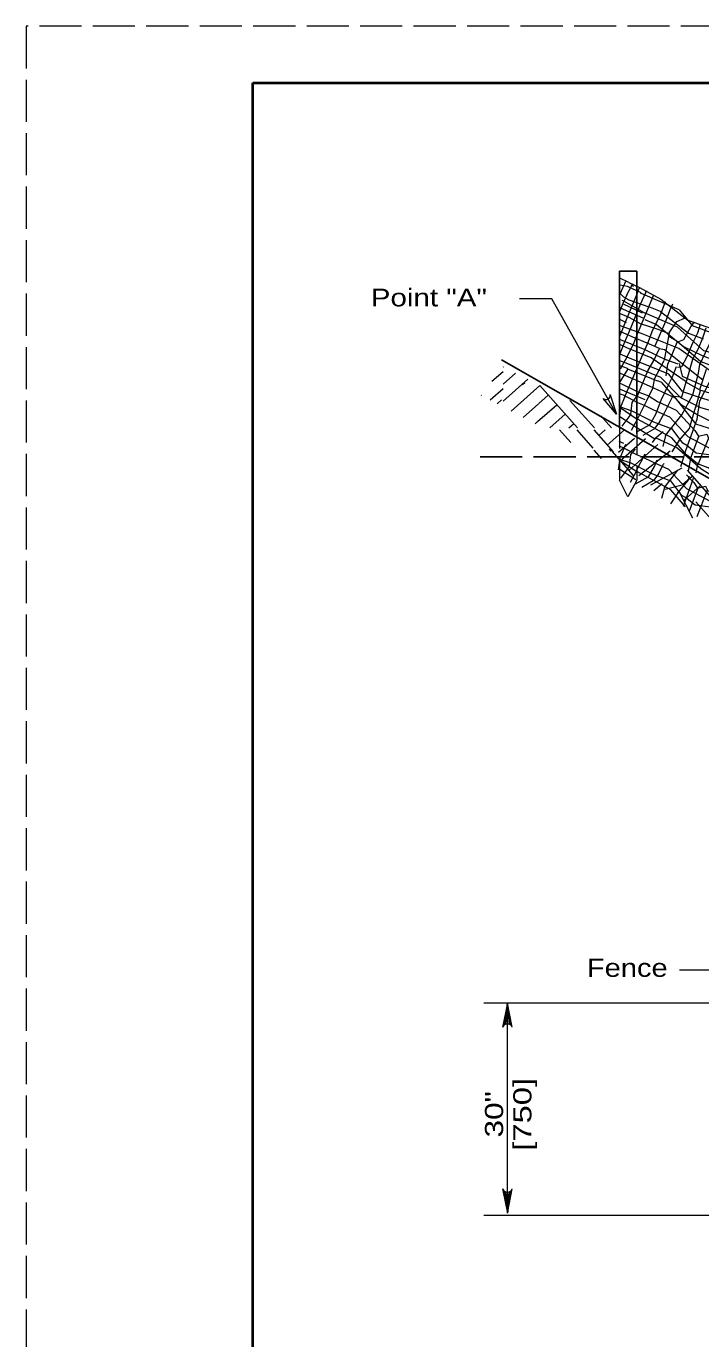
# Model space of a CAD drawing. Extents: x 1083.1 to 1117.1, y 672.5 to 716.5.
# Drawn here: x 1083.13 to 1089.08, y 704.92 to 716.51 of the extents above; entities that cross this region are included whole.
import ezdxf
from ezdxf.enums import TextEntityAlignment as Align

# ---------------------------------------------------------------- set-up
doc = ezdxf.new("R2010")
doc.units = 0
doc.header["$LTSCALE"] = 0.062
doc.linetypes.add('LONG_DASHED', pattern=[7.5, 6, -1.5])
doc.linetypes.add('MEDIUM_DASHED', pattern=[4.5, 3, -1.5])
doc.layers.add('1', color=7, linetype='Continuous', lineweight=13)

msp = doc.modelspace()

# ---------------------------------------------------------------- linework, layer by layer
at = {"layer": '1', "lineweight": 25}
for p, q in [((1085.12642, 716.00825), (1116.62642, 716.00825)), ((1088.51725, 714.345), (1088.36317, 714.345)), ((1088.36317, 714.345), (1088.36317, 712.96758)), ((1088.51725, 714.345), (1088.51725, 712.90917)), ((1091.32058, 711.27967), (1087.3225, 713.56258))]:
    msp.add_line(p, q, dxfattribs=at)
at = {"layer": '1'}
for p, q in [((1088.44675, 714.24658), (1088.36225, 714.28617)), ((1088.421, 714.25992), (1088.36758, 714.14333)), ((1088.398, 714.12), (1088.36092, 714.15842)), ((1088.43333, 714.21175), (1088.36892, 714.221)), ((1088.42842, 714.13725), (1088.4, 714.07233)), ((1088.42842, 714.13725), (1088.47292, 714.21892)), ((1088.55583, 714.15358), (1088.43333, 714.21175)), ((1088.44675, 714.24658), (1088.53967, 714.20158)), ((1088.46475, 714.22258), (1088.48883, 714.21333)), ((1088.47292, 714.21892), (1088.48192, 714.23692)), ((1088.53592, 714.19008), (1088.54733, 714.20208)), ((1088.89, 714.00417), (1088.54867, 714.15125)), ((1088.59575, 714.15667), (1088.6055, 714.17483)), ((1088.36917, 713.99683), (1088.40233, 714.07683)), ((1088.36917, 714.02367), (1088.57142, 713.93317)), ((1088.38592, 714.08875), (1088.4005, 714.08267)), ((1088.398, 714.12), (1088.44633, 714.09375)), ((1088.4005, 714.08267), (1088.58558, 713.9775)), ((1088.567, 713.97425), (1088.4005, 714.054)), ((1088.44633, 714.09375), (1088.62358, 714.0315)), ((1088.49983, 714.02608), (1088.50975, 714.02483)), ((1088.72508, 713.98917), (1088.62358, 714.0315)), ((1088.36917, 713.9715), (1088.44642, 713.93958)), ((1088.36917, 713.919), (1088.42442, 713.893)), ((1088.58742, 713.91933), (1088.69208, 713.87642)), ((1088.89, 714.00417), (1089.00758, 713.86308)), ((1088.36917, 713.86517), (1088.39417, 713.85775)), ((1088.4825, 713.76367), (1088.36917, 713.81192)), ((1088.39417, 713.85775), (1088.54575, 713.802)), ((1088.80208, 713.80267), (1088.75892, 713.56092)), ((1088.99417, 713.85517), (1089.02583, 713.898)), ((1089.19233, 713.79458), (1089.00758, 713.86308)), ((1088.36917, 713.77558), (1088.37042, 713.778)), ((1088.36917, 713.74167), (1088.58683, 713.65442)), ((1088.36917, 713.62033), (1088.41067, 713.72075)), ((1088.36917, 713.6995), (1088.459, 713.65767)), ((1088.45208, 713.57667), (1088.36917, 713.61417)), ((1088.428, 713.58592), (1088.36917, 713.47983)), ((1088.36917, 713.55383), (1088.41892, 713.537)), ((1088.64417, 713.58117), (1088.459, 713.65767)), ((1088.58683, 713.65442), (1088.77617, 713.56433)), ((1088.67025, 713.38817), (1088.75967, 713.55758)), ((1088.88167, 713.52375), (1088.77617, 713.56433)), ((1089.008, 713.5675), (1088.9525, 713.36925)), ((1087.23717, 713.37408), (1087.33567, 713.46117)), ((1087.33567, 713.49842), (1087.33883, 713.50125)), ((1087.33567, 713.34808), (1087.44725, 713.44667)), ((1088.434, 713.48558), (1088.36917, 713.50958)), ((1088.36917, 713.36858), (1088.43817, 713.4775)), ((1088.36917, 713.44517), (1088.62458, 713.3325)), ((1088.41892, 713.537), (1088.72708, 713.40967)), ((1088.43992, 713.482), (1088.434, 713.48558)), ((1088.43992, 713.482), (1088.70042, 713.37658)), ((1088.77617, 713.42058), (1088.79183, 713.52433)), ((1088.83267, 713.4145), (1088.86683, 713.50333)), ((1088.89117, 713.5305), (1088.91658, 713.41975)), ((1089.01133, 713.25308), (1089.06125, 713.445)), ((1089.08083, 713.54992), (1089.27167, 713.47908)), ((1087.33567, 713.19808), (1087.55525, 713.39217)), ((1087.40725, 713.11142), (1087.661, 713.33575)), ((1087.50883, 713.345), (1087.5285, 713.3625)), ((1087.661, 713.33575), (1087.99192, 712.96175)), ((1088.38517, 713.34883), (1088.36917, 713.3555)), ((1088.62458, 713.3325), (1088.8545, 713.22833)), ((1088.67025, 713.38817), (1088.65642, 713.30717)), ((1088.7305, 713.36492), (1088.70042, 713.37658)), ((1088.80033, 713.3485), (1088.83267, 713.4145)), ((1087.14358, 713.25167), (1087.14525, 713.24975)), ((1087.22325, 713.21117), (1087.33567, 713.31058)), ((1087.28533, 713.17575), (1087.32333, 713.20942)), ((1087.30092, 713.22783), (1087.30117, 713.22758)), ((1087.65133, 713.177), (1087.7355, 713.2515)), ((1088.36917, 713.30358), (1088.5875, 713.21342)), ((1088.36917, 713.2635), (1088.39667, 713.25292)), ((1088.40867, 713.23), (1088.3765, 713.15342)), ((1088.62492, 713.2435), (1088.70025, 713.19625)), ((1088.8545, 713.22833), (1089.0345, 712.99783)), ((1088.91325, 713.0785), (1089.01133, 713.25308)), ((1088.92008, 713.285), (1089.0665, 713.23392)), ((1089.07767, 713.28975), (1089.038, 713.15075)), ((1089.0665, 713.23392), (1089.32975, 713.1535)), ((1087.5135, 713.05533), (1087.64792, 713.17425)), ((1087.64158, 713.01808), (1087.81025, 713.16725)), ((1087.92675, 713.20508), (1088.142, 712.96175)), ((1088.3765, 713.15342), (1088.361, 713.05158)), ((1088.5215, 713.03758), (1088.36917, 713.14067)), ((1088.37325, 713.14692), (1088.46542, 713.11667)), ((1088.65042, 713.02192), (1088.46542, 713.11667)), ((1088.5805, 713.16392), (1088.66442, 713.12117)), ((1089.07983, 713.1425), (1089.18583, 713.11217)), ((1087.62008, 712.999), (1087.63817, 713.015)), ((1087.74758, 712.96175), (1087.88475, 713.08308)), ((1087.9175, 712.96175), (1087.95925, 712.99892)), ((1088.19783, 713.0685), (1088.29233, 712.96175)), ((1088.36792, 713.0635), (1088.51792, 712.96483)), ((1088.46308, 713.08358), (1088.38433, 712.97717)), ((1088.5215, 713.03758), (1088.46833, 712.94)), ((1088.63125, 712.99008), (1088.513, 712.92408)), ((1088.65042, 713.02192), (1088.81017, 712.96042)), ((1088.67725, 712.95675), (1088.72367, 713.01767)), ((1088.771, 712.8945), (1088.91325, 713.0785)), ((1087.83575, 712.94533), (1087.9355, 712.8325)), ((1087.98625, 712.94533), (1088.12967, 712.78308)), ((1088.13633, 712.94542), (1088.30758, 712.75158)), ((1088.18108, 712.89458), (1088.2385, 712.94542)), ((1088.25558, 712.81042), (1088.40808, 712.94533)), ((1088.35592, 712.74858), (1088.49525, 712.87192)), ((1088.37083, 712.67158), (1088.59392, 712.86892)), ((1088.6725, 712.953), (1088.57133, 712.89633)), ((1088.67608, 712.86558), (1088.65342, 712.834)), ((1088.751, 712.92825), (1088.67608, 712.86558)), ((1088.771, 712.8945), (1088.74583, 712.79933)), ((1088.9235, 712.82625), (1088.81975, 712.96725)), ((1088.99117, 712.68842), (1089.06717, 712.89383)), ((1089.149, 712.87275), (1089.05617, 712.63517)), ((1088.13767, 712.76542), (1088.2035, 712.691)), ((1088.27267, 712.77533), (1088.28892, 712.75692)), ((1088.29633, 712.75575), (1088.48517, 712.54233)), ((1088.35917, 712.84425), (1088.399, 712.82775)), ((1088.35917, 712.80417), (1088.38667, 712.79358)), ((1088.39867, 712.77067), (1088.3665, 712.69408)), ((1088.39867, 712.77067), (1088.41858, 712.818)), ((1088.43175, 712.76542), (1088.43283, 712.76417)), ((1088.44533, 712.58733), (1088.70233, 712.81433)), ((1088.46483, 712.72692), (1088.50433, 712.77508)), ((1088.53458, 712.54075), (1088.81042, 712.75992)), ((1088.77917, 712.72625), (1088.79792, 712.74283)), ((1088.8885, 712.84925), (1088.82475, 712.75008)), ((1088.3665, 712.69408), (1088.351, 712.59225)), ((1088.5115, 712.57825), (1088.35917, 712.68133)), ((1088.36325, 712.68758), (1088.45542, 712.65733)), ((1088.45308, 712.62425), (1088.46483, 712.72692)), ((1088.64042, 712.56258), (1088.45542, 712.65733)), ((1088.51233, 712.5805), (1088.59, 712.73225)), ((1088.5705, 712.70458), (1088.65442, 712.66183)), ((1088.674, 712.62292), (1088.69575, 712.67942)), ((1088.7025, 712.544), (1088.75392, 712.64175)), ((1088.75392, 712.64175), (1088.75733, 712.64858)), ((1088.93867, 712.73158), (1088.90408, 712.61925)), ((1088.99117, 712.68842), (1088.9695, 712.58425)), ((1089.0515, 712.64625), (1089.03717, 712.56458)), ((1089.17408, 712.722), (1089.04208, 712.73875)), ((1088.35792, 712.60417), (1088.50792, 712.5055)), ((1088.45308, 712.62425), (1088.37433, 712.51783)), ((1088.5115, 712.57825), (1088.45833, 712.48067)), ((1088.62125, 712.53075), (1088.503, 712.46475)), ((1088.62125, 712.53075), (1088.674, 712.62292)), ((1088.64042, 712.56258), (1088.80017, 712.50108)), ((1088.64092, 712.46008), (1088.9185, 712.60967)), ((1088.66725, 712.49742), (1088.71367, 712.55833)), ((1088.761, 712.43517), (1088.87892, 712.58775)), ((1088.92167, 712.46242), (1089.00592, 712.53692)), ((1088.92867, 712.27225), (1089.01775, 712.51833)), ((1088.95692, 712.54875), (1089.01942, 712.48033)), ((1088.96008, 712.58867), (1089.1935, 712.32483)), ((1088.97117, 712.49892), (1088.982, 712.53617)), ((1088.6625, 712.49367), (1088.56133, 712.437)), ((1088.741, 712.46892), (1088.66608, 712.40625)), ((1088.761, 712.43517), (1088.73583, 712.34)), ((1088.76592, 712.42067), (1088.91825, 712.45958)), ((1088.9135, 712.36692), (1088.80975, 712.50792)), ((1088.8785, 712.38992), (1088.97117, 712.49892)), ((1088.88675, 712.4045), (1089.00992, 712.16942)), ((1088.93617, 712.32483), (1089.08067, 712.45267)), ((1088.98117, 712.22908), (1089.05717, 712.4345)), ((1089.139, 712.41342), (1089.04617, 712.17583)), ((1088.8785, 712.38992), (1088.81475, 712.29075)), ((1089.16408, 712.26267), (1089.03208, 712.27942)), ((1089.037, 712.30875), (1089.26092, 712.05567)), ((1089.79942, 707.88417), (1087.16658, 707.88417)), ((1087.34792, 707.69067), (1087.375, 707.88417)), ((1087.36133, 707.69717), (1087.375, 707.88417)), ((1087.375, 706.03092), (1087.375, 707.88417)), ((1087.375, 707.69917), (1087.375, 707.88417)), ((1087.39242, 707.69575), (1087.375, 707.88417)), ((1087.40492, 707.68833), (1087.375, 707.88417)), ((1087.375, 707.70575), (1087.375, 707.8815)), ((1087.34508, 706.22675), (1087.375, 706.03092)), ((1087.35758, 706.21933), (1087.375, 706.03092)), ((1087.40208, 706.22442), (1087.375, 706.03092)), ((1087.38867, 706.21792), (1087.375, 706.03092)), ((1087.375, 706.21592), (1087.375, 706.03092)), ((1087.375, 706.20933), (1087.375, 706.03358)), ((1089.79942, 706.00833), (1087.16658, 706.00833))]:
    msp.add_line(p, q, dxfattribs=at)
at = {"layer": '1', "linetype": 'MEDIUM_DASHED'}
msp.add_line((1088.36317, 712.96758), (1088.36317, 712.50075), dxfattribs=at)
at = {"layer": '1', "linetype": 'LONG_DASHED', "lineweight": 25}
msp.add_line((1087.134, 712.706), (1099.63158, 712.706), dxfattribs=at)
at = {"layer": '1', "linetype": 'LONG_DASHED'}
msp.add_lwpolyline([(1083.12642, 694.50825), (1117.12642, 694.50825), (1117.12642, 716.50825), (1083.12642, 716.50825)], close=True, dxfattribs=at)
at = {"layer": '1', "lineweight": 25}
msp.add_lwpolyline([(1116.62642, 695.00825), (1085.12642, 695.00825), (1085.12642, 716.00825)], dxfattribs=at)
at = {"layer": '1', "lineweight": 40}
msp.add_lwpolyline([(1085.12642, 716.00825), (1116.62642, 716.00825), (1116.62642, 695.00825), (1085.12642, 695.00825)], close=True, dxfattribs=at)
msp.add_lwpolyline([(1085.12642, 716.00825), (1116.62642, 716.00825), (1116.62642, 695.00825), (1085.12642, 695.00825)], close=True, dxfattribs=at)
at = {"layer": '1'}
for points in [[(1088.37042, 713.778), (1088.42475, 713.91917), (1088.51925, 714.14683), (1088.53592, 714.19008)], [(1088.428, 713.58592), (1088.4865, 713.702), (1088.53858, 713.82833), (1088.66767, 714.13675)], [(1088.54033, 714.2015), (1088.72958, 714.09983), (1088.96775, 713.91233), (1089.18442, 713.83683)], [(1088.54933, 714.05425), (1088.59575, 714.15667), (1088.59017, 714.1565)], [(1088.339, 713.08425), (1087.7675, 714.10217), (1087.48133, 714.10217)], [(1088.40867, 713.23), (1088.48917, 713.42125), (1088.553, 713.56917), (1088.62042, 713.72625), (1088.65375, 713.81275), (1088.73058, 713.97658), (1088.77008, 714.07908)], [(1088.41067, 713.72075), (1088.46225, 713.83683), (1088.54933, 714.05425)], [(1088.67583, 713.68142), (1088.71867, 713.77467), (1088.7725, 713.90558), (1088.81367, 714.01258), (1088.83425, 714.057)], [(1088.44642, 713.93958), (1088.54667, 713.88533), (1088.703, 713.833), (1088.78442, 713.80167), (1088.80583, 713.76733), (1088.87375, 713.72808), (1089.08083, 713.54992)], [(1090.13217, 713.17925), (1089.97158, 713.23842), (1089.8795, 713.287), (1089.6165, 713.40392), (1089.26675, 713.60125), (1089.10992, 713.64333), (1088.87575, 713.85017), (1088.58558, 713.9775)], [(1088.72508, 713.98917), (1088.97225, 713.79825), (1089.10183, 713.74833)], [(1088.80208, 713.80267), (1088.87133, 713.90158), (1088.93725, 713.932)], [(1089.1955, 713.44308), (1088.88675, 713.66292), (1088.55092, 713.79742)], [(1088.69208, 713.87642), (1088.92858, 713.6815), (1089.09417, 713.60242), (1089.33058, 713.51058)], [(1088.79183, 713.52433), (1088.82817, 713.60967), (1088.87325, 713.71783), (1088.9335, 713.74258), (1088.99417, 713.85517)], [(1088.87592, 713.49983), (1088.91442, 713.50417), (1088.95983, 713.58608), (1089.01275, 713.71467), (1089.05683, 713.80225), (1089.07892, 713.87742)], [(1089.008, 713.5675), (1089.06258, 713.66417), (1089.0985, 713.7575), (1089.12875, 713.84517)], [(1089.06125, 713.445), (1089.07333, 713.52142), (1089.1245, 713.62725), (1089.19525, 713.77517), (1089.20633, 713.831)], [(1088.71717, 713.66283), (1088.60733, 713.71033), (1088.4825, 713.76367)], [(1088.92008, 713.285), (1088.8, 713.4375), (1088.45208, 713.57667)], [(1088.46308, 713.08358), (1088.47483, 713.18625), (1088.527, 713.24983), (1088.55858, 713.33175), (1088.61325, 713.465), (1088.666, 713.55708), (1088.71717, 713.66283), (1088.762, 713.65342)], [(1088.7125, 713.00333), (1088.76392, 713.10108), (1088.836, 713.24333), (1088.9155, 713.23717), (1088.9525, 713.36925), (1088.64417, 713.58117)], [(1088.762, 713.65342), (1089.10067, 713.38542), (1089.08608, 713.4015)], [(1088.93867, 712.73158), (1089.05, 713.039), (1089.07467, 713.202), (1089.2, 713.44658)], [(1089.12967, 713.47883), (1089.07033, 713.29775), (1088.95075, 713.36475)], [(1088.62492, 713.2435), (1088.52158, 713.28067), (1088.38517, 713.34883)], [(1088.63125, 712.99008), (1088.684, 713.08225), (1088.73217, 713.20742), (1088.80033, 713.3485)], [(1088.72708, 713.40967), (1088.90383, 713.2295), (1089.07983, 713.1425)], [(1088.7305, 713.36492), (1088.90217, 713.17267), (1089.05442, 713.0765), (1089.0595, 713.07192)], [(1088.91658, 713.41975), (1089.108, 713.33283), (1089.31533, 713.27225), (1089.44858, 713.22017)], [(1088.28225, 713.25558), (1088.339, 713.08425), (1088.22067, 713.22058), (1088.22075, 713.22058)], [(1088.39667, 713.25292), (1088.52317, 713.18592), (1088.5805, 713.16392)], [(1089.30833, 712.51342), (1089.14792, 712.60917), (1089.0515, 712.64625), (1088.957, 712.7245), (1088.82608, 712.87592), (1088.67725, 712.95675), (1088.52233, 713.03983), (1088.60617, 713.20367), (1088.65642, 713.30717)], [(1089.07033, 713.29775), (1089.26642, 713.24058), (1089.26283, 713.24833)], [(1088.66442, 713.12117), (1088.80642, 713.05858), (1088.967, 712.88533), (1089.21392, 712.75367)], [(1088.70025, 713.19625), (1088.86458, 713.11992), (1089.02942, 712.93967), (1089.0615, 712.88817), (1089.13458, 712.90708), (1089.15333, 712.86592), (1089.24675, 712.82992)], [(1089.00233, 713.03117), (1089.038, 713.15075), (1089.03775, 713.14292)], [(1088.8885, 712.84925), (1088.98117, 712.95825), (1089.00233, 713.03117)], [(1089.0345, 712.99783), (1089.14567, 712.96292), (1089.26533, 712.91425)], [(1089.05442, 713.0765), (1089.17358, 713.0175), (1089.25883, 712.98733)], [(1088.51792, 712.96483), (1088.67608, 712.86558), (1088.69042, 712.87208)], [(1088.68508, 712.87592), (1088.87133, 712.79025), (1089.08342, 712.60383), (1089.28167, 712.47617), (1089.42475, 712.40333), (1089.64542, 712.30958)], [(1088.38667, 712.79358), (1088.51317, 712.72658), (1088.5705, 712.70458)], [(1089.04208, 712.73875), (1088.9575, 712.80683), (1088.9235, 712.82625)], [(1088.65442, 712.66183), (1088.79642, 712.59925), (1088.957, 712.426), (1089.20392, 712.29433)], [(1088.947, 712.26517), (1088.81608, 712.41658), (1088.66725, 712.49742), (1088.51233, 712.5805)], [(1089.01942, 712.48033), (1089.0515, 712.42883), (1089.12458, 712.44775), (1089.14333, 712.40658), (1089.23675, 712.37058)], [(1089.03208, 712.27942), (1088.9475, 712.3475), (1088.9135, 712.36692)], [(1089.90975, 707.54325), (1089.27583, 708.17617), (1088.893, 708.17617)], [(1087.41775, 707.67042), (1087.375, 707.88417), (1087.33225, 707.67042)], [(1087.33225, 706.24467), (1087.375, 706.03092), (1087.41775, 706.24467)]]:
    msp.add_lwpolyline(points, dxfattribs=at)
at = {"layer": '1', "linetype": 'MEDIUM_DASHED'}
msp.add_lwpolyline([(1088.51725, 712.90917), (1088.51725, 712.50075), (1088.437, 712.35375), (1088.36317, 712.50075)], dxfattribs=at)
at = {"layer": '1'}
for centre, radius, start, end in [((1088.24438, 713.25067), 0.0382, 231.74452, 7.57065), ((1087.37495, 707.65316), 0.04613, 22.08605, 157.91218), ((1087.37505, 706.26191), 0.04613, 202.08605, 337.91218)]:
    msp.add_arc(centre, radius, start, end, dxfattribs=at)

# ---------------------------------------------------------------- texts
for s, height, width, p in [('Point "A"', 0.156, 1.25, (1086.16792, 714.03517)), ('Fence', 0.16, 1.2, (1088.076, 708.116))]:
    msp.add_text(s, height=height, dxfattribs=dict(at, width=width)).set_placement(p)
for s, width, p in [('[750]', 1.35, (1087.58633, 706.90212)), ('30"', 1.3, (1087.33633, 706.90212))]:
    msp.add_text(s, height=0.16, rotation=90, dxfattribs=dict(at, width=width)).set_placement(p, align=Align.CENTER)

doc.saveas('drawing.dxf')
